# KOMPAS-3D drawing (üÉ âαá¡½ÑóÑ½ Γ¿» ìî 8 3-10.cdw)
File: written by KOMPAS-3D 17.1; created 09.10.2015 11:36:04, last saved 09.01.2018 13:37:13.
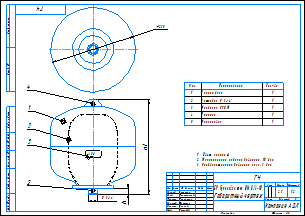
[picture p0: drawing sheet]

Sheet 1: A3, landscape

Title block, sheet 1: name: БР Гранлевел тип НМ 8/3-10 / Габаритный чертеж; mass: 2,1; scale: 1:2; sheets: 1; organisation: Компания АДЛ; cell 10: Нач.отд.; sheet format: A3; stored path: \\Fsk1.adlc.lan\files\АП\20_PKO\02_Насосное направление\АУПД\Чертежи на баки\Чертеж.cdw; drawn by: Лощинин; checked by: Хантимеров; technical control: Курлыкина; cell 113: Щетинин; standards control: Долгов; approved by: Рашидов

Views: Вид 1, Спереди, Проекционный вид 2
Referenced files in \\Fsk1\FILES\АП\20_PKO\02_Насосное направление\Разработка\04_Проекты разные\Баки\КД действующая\flexcon r_dwg\Компас\: 8 литров.a3d
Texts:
  ADL
  romans
  romand
  romant
  АДЛ
  Flexcon R8_1.5-6
  TRAZO_Y_PUNTOX2_RGB_0_255_0_SC_2_THICK_0.05
  TRAZO_Y_PUNTOX2_RGB_0_255_0_SC_1_THICK_0.05
  TRAZO_Y_PUNTOX2_RGB_0_255_0_SC_0.3_THICK_0.05
  POLYLINE_STYLE_0.30_RGB_0_0_0
  ACAD_ISO03W100_RGB_223_127_255_SC_0.5_THICK_0.05
  ACAD_ISO03W100_RGB_223_127_255_SC_1_THICK_0.05
  TRAZO_Y_PUNTOX2_RGB_0_255_0_SC_0.25_THICK_0.05
  СONTINUOUS_RGB_223_127_255_THICK_0.05
  ACAD_ISO03W100_RGB_223_127_255_SC_0.25_THICK_0.05
  TRAZO_Y_PUNTOX2_RGB_0_255_0_SC_3_THICK_0.05
  POLYLINE_STYLE_0.35_RGB_0_0_0
  TRAZO_Y_PUNTOX2_RGB_0_255_0_SC_0.5_THICK_0.05
  TRAZO_Y_PUNTOX2_RGB_0_255_0_SC_0.4_THICK_0.05
  ACAD_ISO03W100_RGB_223_127_255_SC_0.046_THICK_0.05
  ACAD_ISO03W100_RGB_223_127_255_SC_0.24_THICK_0.05
  ACAD_ISO03W100_RGB_223_127_255_SC_0.15_THICK_0.05
  ACAD_ISO03W100_RGB_223_127_255_SC_0.0081_THICK_0.05
  ACAD_ISO03W100_RGB_223_127_255_SC_0.0092_THICK_0.05
  ACAD_ISO03W100_RGB_223_127_255_SC_0.14_THICK_0.05
  ACAD_ISO03W100_RGB_223_127_255_SC_0.16_THICK_0.05
  ACAD_ISO03W100_RGB_223_127_255_SC_0.31_THICK_0.05
  ACAD_ISO03W100_RGB_223_127_255_SC_0.47_THICK_0.05
  ACAD_ISO03W100_RGB_223_127_255_SC_0.26_THICK_0.05
  ACAD_ISO03W100_RGB_223_127_255_SC_0.36_THICK_0.05
  CONTINUOUS_RGB_0_0_0_THICK_0.3
  ACAD_ISO03W100_RGB_223_127_255_SC_0.027_THICK_0.05
  ACAD_ISO03W100_RGB_223_127_255_SC_0.18_THICK_0.05
  ACAD_ISO03W100_RGB_223_127_255_SC_0.4_THICK_0.05
  ACAD_ISO03W100_RGB_223_127_255_SC_0.016_THICK_0.05
  ACAD_ISO03W100_RGB_223_127_255_SC_0.057_THICK_0.05
  ACAD_ISO03W100_RGB_223_127_255_SC_0.23_THICK_0.05
  ACAD_ISO03W100_RGB_223_127_255_SC_0.011_THICK_0.05
  ACAD_ISO03W100_RGB_223_127_255_SC_0.42_THICK_0.05
  ACAD_ISO03W100_RGB_223_127_255_SC_0.29_THICK_0.05
  ACAD_ISO03W100_RGB_223_127_255_SC_0.061_THICK_0.05
  ACAD_ISO03W100_RGB_223_127_255_SC_0.32_THICK_0.05
  ACAD_ISO03W100_RGB_223_127_255_SC_0.002_THICK_0.05
  ACAD_ISO03W100_RGB_223_127_255_SC_0.065_THICK_0.05
  ACAD_ISO03W100_RGB_223_127_255_SC_0.28_THICK_0.05
  ACAD_ISO03W100_RGB_223_127_255_SC_0.058_THICK_0.05
  ACAD_ISO03W100_RGB_223_127_255_SC_0.022_THICK_0.05
  ACAD_ISO03W100_RGB_223_127_255_SC_0.0055_THICK_0.05
  ACAD_ISO03W100_RGB_223_127_255_SC_0.19_THICK_0.05
  ACAD_ISO03W100_RGB_223_127_255_SC_0.22_THICK_0.05
  ACAD_ISO03W100_RGB_223_127_255_SC_0.12_THICK_0.05
  ACAD_ISO03W100_RGB_223_127_255_SC_0.21_THICK_0.05
  ACAD_ISO03W100_RGB_223_127_255_SC_0.1_THICK_0.05
  CONTINUOUS_RGB_255_223_127_THICK_0.15
  ACAD_ISO03W100_RGB_223_127_255_SC_0.085_THICK_0.05
  ACAD_ISO03W100_RGB_223_127_255_SC_0.026_THICK_0.05
  ACAD_ISO03W100_RGB_223_127_255_SC_0.05_THICK_0.05
  ACAD_ISO03W100_RGB_223_127_255_SC_0.3_THICK_0.05
  ACAD_ISO03W100_RGB_223_127_255_SC_0.33_THICK_0.05
  ACAD_ISO03W100_RGB_223_127_255_SC_0.49_THICK_0.05
  ACAD_ISO03W100_RGB_223_127_255_SC_0.37_THICK_0.05
  ACAD_ISO03W100_RGB_223_127_255_SC_0.035_THICK_0.05
  ACAD_ISO03W100_RGB_223_127_255_SC_0.018_THICK_0.05
  ACAD_ISO03W100_RGB_223_127_255_SC_0.45_THICK_0.05
  ACAD_ISO03W100_RGB_223_127_255_SC_0.051_THICK_0.05
  CONTINUOUS_RGB_255_0_0_THICK_0.05
  CONTINUOUS_RGB_255_191_0_THICK_0.05
  TRAZO_Y_PUNTOX2_RGB_0_255_0_SC_0.13_THICK_0.05
  CONTINUOUS_RGB_191_255_127_THICK_0.05
  ACAD_ISO03W100_RGB_223_127_255_SC_0.042_THICK_0.05
  ACAD_ISO03W100_RGB_223_127_255_SC_0.27_THICK_0.05
  ACAD_ISO03W100_RGB_223_127_255_SC_0.0016_THICK_0.05
  ACAD_ISO03W100_RGB_223_127_255_SC_0.099_THICK_0.05
  ACAD_ISO03W100_RGB_223_127_255_SC_0.0058_THICK_0.05
  ACAD_ISO03W100_RGB_223_127_255_SC_0.0074_THICK_0.05
  ACAD_ISO03W100_RGB_223_127_255_SC_0.088_THICK_0.05
  ACAD_ISO03W100_RGB_223_127_255_SC_0.0023_THICK_0.05
  ACAD_ISO03W100_RGB_223_127_255_SC_0.38_THICK_0.05
  ACAD_ISO03W100_RGB_223_127_255_SC_0.093_THICK_0.05
  ACAD_ISO03W100_RGB_223_127_255_SC_0.34_THICK_0.05
  ACAD_ISO03W100_RGB_223_127_255_SC_0.087_THICK_0.05
  ACAD_ISO03W100_RGB_223_127_255_SC_0.015_THICK_0.05
  ACAD_ISO03W100_RGB_223_127_255_SC_0.2_THICK_0.05
  ACAD_ISO03W100_RGB_223_127_255_SC_0.41_THICK_0.05
  ACAD_ISO03W100_RGB_223_127_255_SC_0.35_THICK_0.05
  ACAD_ISO03W100_RGB_223_127_255_SC_0.0006_THICK_0.05
  ACAD_ISO03W100_RGB_223_127_255_SC_0.012_THICK_0.05
  CONTINUOUS_RGB_255_223_127_THICK_0.05
  TRAZO_Y_PUNTOX2_RGB_0_255_0_SC_0.35_THICK_0.05
  TRAZO_Y_PUNTOX2_RGB_0_255_0_SC_0.2_THICK_0.05
  TRAZO_Y_PUNTOX2_RGB_0_255_0_SC_0.08_THICK_0.05
  ACAD_ISO03W100_RGB_223_127_255_SC_0.8_THICK_0.05
  TRAZO_Y_PUNTOX2_RGB_0_255_0_SC_0.75_THICK_0.05
  ACAD_ISO03W100_RGB_223_127_255_SC_0.13_THICK_0.05
  ACAD_ISO03W100_RGB_223_127_255_SC_0.063_THICK_0.05
  TRAZO_Y_PUNTOX2_RGB_0_255_0_SC_0.11_THICK_0.05
  HOUND_ISO 0
  HOUND_ISO 1
  ANGLE_ISO 0
  ANGLE_ISO 1
  AR-CONC_ISO
  AR-CONC_ISO 0
  AR-CONC_ISO 1
  AR-CONC_ISO 2
  AR-CONC_ISO 3
  AR-CONC_ISO 4
  AR-CONC_ISO 5
  AR-CONC_ISO 6
  AR-CONC_ISO 7
  AR-CONC_ISO 8
  AR-CONC_ISO 9
  AR-CONC_ISO 10
  AR-CONC_ISO 11
  AR-CONC_ISO 12
  ANSI38_ISO 1
Dimensions and other numbers on the sheet: 261; 16; 25300_Flexcon R8_1.5; 235; 1:2; 1; 2,1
